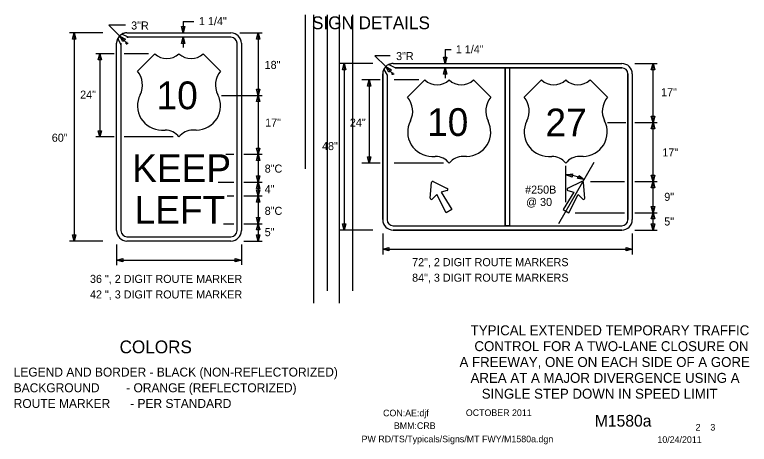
# Model space of a CAD drawing. Extents: x 16728 to 19508, y 5553 to 7079.
# Drawn here: x 17774 to 18463, y 5932 to 6334 of the extents above; entities that cross this region are included whole.
import ezdxf

# ---------------------------------------------------------------- set-up
doc = ezdxf.new("R2010")
doc.units = 0
for name, color, linetype in [('ALI_LEGAL_EX', 7, 'Continuous'), ('BORDER', 7, 'Continuous'), ('BORDER_SIGNAL_WO', 7, 'Continuous'), ('TRAFFIC_SIGNS_PR', 7, 'Continuous'), ('TYPICAL_EX', 7, 'Continuous'), ('TYPICAL_TEXT_DIMEN_PR', 7, 'Continuous')]:
    doc.layers.add(name, color=color, linetype=linetype)

msp = doc.modelspace()

# ---------------------------------------------------------------- linework, layer by layer
at = {"layer": 'ALI_LEGAL_EX'}
for p, q in [((18046.81, 6189.84), (18046.81, 6334.29)), ((18054.48, 6334.29), (18054.48, 6206.79)), ((18054.48, 6334.29), (18054.48, 6063.94)), ((18067.45, 6075.61), (18067.45, 6334.29)), ((18078.48, 6334.29), (18078.48, 6206.79)), ((18078.48, 6334.29), (18078.48, 6063.94)), ((18091.45, 6075.61), (18091.45, 6334.29))]:
    msp.add_line(p, q, dxfattribs=at)
at = {"layer": 'TRAFFIC_SIGNS_PR'}
for p, q in [((17879.58, 6317.25), (17977.08, 6317.25)), ((17872, 6313.63), (17870.99, 6312.12)), ((17871.02, 6312.05), (17873.89, 6306.01)), ((17880.78, 6313.18), (17874.69, 6315.93)), ((17977.08, 6313.18), (17879.58, 6313.18)), ((17869.83, 6132), (17869.83, 6307.5)), ((17873.89, 6307.5), (17873.89, 6132)), ((17982.77, 6132), (17982.77, 6307.5)), ((17986.83, 6307.5), (17986.83, 6132)), ((18120.27, 6282.81), (18123.41, 6277.76)), ((18131.06, 6284.5), (18124.82, 6287.51)), ((18129.1, 6288.55), (18343.6, 6288.55)), ((18129.1, 6288.55), (18343.6, 6288.55)), ((18131.04, 6284.49), (18234.32, 6284.49)), ((18343.6, 6284.49), (18131.04, 6284.49)), ((18234.32, 6284.49), (18234.32, 6136.61)), ((18238.38, 6284.49), (18238.38, 6136.61)), ((18238.38, 6284.49), (18343.6, 6284.49)), ((18119.35, 6278.8), (18119.35, 6142.3)), ((18119.35, 6142.3), (18119.35, 6278.8)), ((18123.41, 6277.75), (18123.41, 6142.3)), ((18123.41, 6277.75), (18123.41, 6142.3)), ((18349.29, 6278.8), (18349.29, 6233.05)), ((18349.29, 6142.3), (18349.29, 6278.8)), ((18353.35, 6278.8), (18353.35, 6142.3)), ((18353.35, 6278.8), (18353.35, 6142.3)), ((18349.29, 6233.05), (18349.29, 6142.3)), ((18163.95, 6162.41), (18165.1, 6177.12)), ((18166.62, 6177.99), (18179.93, 6171.63)), ((18306.08, 6177.99), (18292.77, 6171.63)), ((18308.75, 6162.41), (18307.6, 6177.12)), ((18129.1, 6136.61), (18343.6, 6136.61)), ((18129.1, 6132.55), (18343.6, 6132.55)), ((18343.6, 6132.55), (18129.1, 6132.55)), ((17879.58, 6126.31), (17977.08, 6126.31)), ((17977.08, 6122.25), (17879.58, 6122.25))]:
    msp.add_line(p, q, dxfattribs=at)
for points in [[(18131.04, 6284.49), (18131.03, 6284.49)], [(18123.41, 6277.76), (18123.41, 6277.75)], [(18179.77, 6169.66), (18174.04, 6168.09), (18184.26, 6151.92), (18178.86, 6148.8), (18169.97, 6165.74), (18165.74, 6161.57)], [(18292.93, 6169.66), (18298.66, 6168.09), (18288.44, 6151.92), (18293.84, 6148.8), (18302.73, 6165.74), (18306.96, 6161.57)]]:
    msp.add_lwpolyline(points, dxfattribs=at)
msp.add_lwpolyline([(18234.32, 6284.49), (18238.38, 6284.49), (18238.38, 6136.61), (18234.32, 6136.61)], close=True, dxfattribs=at)
for centre, radius, start, end in [((17879.58, 6307.5), 9.75, 90, 180), ((17878.99, 6309.67), 7.6, 85.58319, 124.53531), ((17977.08, 6307.5), 9.75, 0, 90), ((17876.86, 6308.09), 7.06, 145.86811, 184.82317), ((17880.18, 6317.61), 4.47, 262.2432, 277.7568), ((17977.08, 6307.5), 5.69, 0, 90), ((17868.43, 6306.75), 5.51, 352.24294, 7.75653), ((18125.48, 6279.5), 6.17, 147.60925, 186.56283), ((18129.1, 6278.8), 9.75, 90, 180), ((18129.1, 6278.8), 9.75, 90, 180), ((18128.42, 6281.98), 6.6, 84.11162, 123.06374), ((18130.04, 6291.67), 7.24, 277.81035, 278.05403), ((18343.6, 6278.8), 9.75, 0, 90), ((18343.6, 6278.8), 9.75, 0, 90), ((18343.6, 6278.8), 5.69, 0, 89.99421), ((18343.6, 6278.8), 5.69, 0, 90), ((18166.16, 6177.04), 1.06, 64.48226, 175.51774), ((18306.54, 6177.04), 1.06, 4.48226, 115.51774), ((18179.47, 6170.68), 1.06, 285.9885, 64.48226), ((18293.23, 6170.68), 1.06, 115.51774, 254.0115), ((18165.01, 6162.33), 1.06, 175.51775, 314.01151), ((18307.69, 6162.33), 1.06, 225.98849, 4.48225), ((18129.1, 6142.3), 9.75, 180, 270), ((18129.1, 6142.3), 9.75, 180, 270), ((18129.1, 6142.3), 5.69, 180, 270), ((18129.1, 6142.3), 5.69, 180, 270), ((18343.6, 6142.3), 9.75, 270, 0), ((18343.6, 6142.3), 5.69, 270, 0), ((18343.6, 6142.3), 9.75, 270, 0), ((18343.6, 6142.3), 5.69, 270, 0), ((17879.58, 6132), 9.75, 180, 270), ((17879.58, 6132), 5.69, 180, 270), ((17977.08, 6132), 5.69, 270, 0), ((17977.08, 6132), 9.75, 270, 0)]:
    msp.add_arc(centre, radius, start, end, dxfattribs=at)
at = {"layer": 'TYPICAL_EX'}
for p, q in [((17889.33, 6281.5), (17905.58, 6297.75)), ((17967.33, 6281.5), (17951.08, 6297.75)), ((18142.71, 6256.89), (18158.96, 6273.14)), ((18220.71, 6256.89), (18204.46, 6273.14)), ((18251.99, 6256.89), (18268.24, 6273.14)), ((18329.99, 6256.89), (18313.74, 6273.14)), ((17912.06, 6226.21), (17915.31, 6226.21)), ((17944.6, 6226.21), (17941.35, 6226.21)), ((18165.44, 6201.6), (18168.69, 6201.6)), ((18197.98, 6201.6), (18194.73, 6201.6)), ((18274.72, 6201.6), (18277.97, 6201.6)), ((18307.26, 6201.6), (18304.01, 6201.6))]:
    msp.add_line(p, q, dxfattribs=at)
for centre, radius, start, end in [((17916.95, 6309.58), 16.42, 226.14041, 313.85958), ((17939.7, 6309.59), 16.42, 226.14042, 313.85959), ((17873.93, 6268.49), 20.16, 333.09768, 40.19361), ((17982.73, 6268.49), 20.16, 139.80639, 206.90233), ((18170.34, 6284.97), 16.42, 226.14041, 313.85958), ((18193.09, 6284.97), 16.42, 226.14042, 313.85959), ((18279.62, 6284.97), 16.42, 226.14041, 313.85958), ((18302.36, 6284.97), 16.42, 226.14042, 313.85959), ((17912.1, 6248.93), 22.73, 152.6698, 269.90132), ((17944.56, 6248.93), 22.73, 270.09868, 27.3302), ((18127.31, 6243.88), 20.16, 333.09768, 40.19361), ((18236.11, 6243.88), 20.16, 139.80639, 206.90233), ((18236.59, 6243.88), 20.16, 333.09768, 40.19361), ((18345.39, 6243.88), 20.16, 139.80639, 206.90233), ((18165.48, 6224.32), 22.73, 152.6698, 269.90132), ((18197.94, 6224.32), 22.73, 270.09868, 27.3302), ((18274.76, 6224.32), 22.73, 152.6698, 269.90132), ((18307.22, 6224.32), 22.73, 270.09868, 27.3302), ((17915.35, 6209.93), 16.28, 37.1038, 90.13853), ((17941.31, 6209.93), 16.28, 89.86147, 142.8962), ((18168.73, 6185.32), 16.28, 37.1038, 90.13853), ((18194.69, 6185.32), 16.28, 89.86147, 142.8962), ((18278.01, 6185.32), 16.28, 37.1038, 90.13853), ((18303.97, 6185.32), 16.28, 89.86147, 142.8962)]:
    msp.add_arc(centre, radius, start, end, dxfattribs=at)
at = {"layer": 'TYPICAL_TEXT_DIMEN_PR'}
for p, q in [((17878.2, 6324.53), (17862.54, 6324.53)), ((17862.54, 6324.53), (17872.78, 6314.29)), ((17932.3, 6328.01), (17932.3, 6317.25)), ((17932.3, 6328.01), (17942.41, 6328.01)), ((17857, 6317.25), (17825.71, 6317.25)), ((17828.47, 6311.38), (17830.04, 6317.25)), ((17830.04, 6317.25), (17830.04, 6122.25)), ((17830.04, 6317.25), (17831.62, 6311.38)), ((17932.3, 6317.25), (17930.73, 6323.11)), ((17930.73, 6323.11), (17932.3, 6323.11)), ((17932.3, 6323.11), (17933.87, 6323.11)), ((17933.87, 6323.11), (17932.3, 6317.25)), ((17985.37, 6317.25), (18006.33, 6317.25)), ((18000.86, 6311.38), (18002.43, 6317.25)), ((18002.43, 6317.25), (18002.43, 6258.75)), ((18002.43, 6317.25), (18004, 6311.38)), ((17830.04, 6311.38), (17828.47, 6311.38)), ((17831.62, 6311.38), (17830.04, 6311.38)), ((17872.78, 6314.29), (17879.34, 6307.74)), ((17875.81, 6309.04), (17872.78, 6314.29)), ((17872.78, 6314.29), (17878.04, 6311.26)), ((17876.92, 6310.15), (17875.81, 6309.04)), ((17878.04, 6311.26), (17876.92, 6310.15)), ((17930.78, 6307.32), (17932.35, 6313.18)), ((17932.35, 6313.18), (17932.35, 6303.43)), ((17932.35, 6313.18), (17933.92, 6307.32)), ((18002.43, 6311.38), (18000.86, 6311.38)), ((18004, 6311.38), (18002.43, 6311.38)), ((17878.13, 6307.74), (17880.55, 6307.74)), ((17879.34, 6306.53), (17879.34, 6308.95)), ((17932.35, 6307.32), (17930.78, 6307.32)), ((17933.92, 6307.32), (17932.35, 6307.32)), ((17867.46, 6297.75), (17850.33, 6297.75)), ((17852.65, 6291.88), (17854.23, 6297.75)), ((17854.23, 6297.75), (17854.23, 6219.75)), ((17854.23, 6297.75), (17855.8, 6291.88)), ((17899.7, 6297.75), (17876.82, 6297.75)), ((18126.24, 6295.83), (18112.06, 6295.83)), ((18112.06, 6295.83), (18122.21, 6285.69)), ((18177.96, 6301.7), (18177.96, 6288.55)), ((18177.96, 6301.7), (18183.48, 6301.7)), ((17854.23, 6291.88), (17852.65, 6291.88)), ((17855.8, 6291.88), (17854.23, 6291.88)), ((18177.96, 6288.55), (18176.39, 6294.41)), ((18176.39, 6294.41), (18177.96, 6294.41)), ((18177.96, 6294.41), (18179.53, 6294.41)), ((18179.53, 6294.41), (18177.96, 6288.55)), ((18110.12, 6288.55), (18078.82, 6288.55)), ((18081.59, 6282.69), (18083.16, 6288.55)), ((18083.16, 6282.69), (18081.59, 6282.69)), ((18083.16, 6288.55), (18083.16, 6132.55)), ((18083.16, 6288.55), (18084.73, 6282.69)), ((18084.73, 6282.69), (18083.16, 6282.69)), ((18122.21, 6285.69), (18128.86, 6279.04)), ((18125.25, 6280.43), (18122.21, 6285.68)), ((18122.21, 6285.68), (18127.47, 6282.65)), ((18127.47, 6282.65), (18126.36, 6281.54)), ((18176.44, 6278.62), (18178.01, 6284.49)), ((18176.44, 6278.62), (18178.01, 6284.49)), ((18178.01, 6284.49), (18178.01, 6274.74)), ((18178.01, 6284.49), (18179.58, 6278.62)), ((18178.01, 6284.49), (18179.58, 6278.62)), ((18355.72, 6288.55), (18376.68, 6288.55)), ((18371.22, 6282.69), (18372.79, 6288.55)), ((18372.79, 6282.69), (18371.22, 6282.69)), ((18372.78, 6288.55), (18372.78, 6233.3)), ((18372.79, 6288.55), (18374.36, 6282.69)), ((18374.36, 6282.69), (18372.79, 6282.69)), ((18126.36, 6281.54), (18125.25, 6280.43)), ((18127.65, 6279.04), (18130.07, 6279.04)), ((18128.86, 6277.83), (18128.86, 6280.25)), ((18178.01, 6278.62), (18176.44, 6278.62)), ((18178.01, 6278.62), (18176.44, 6278.62)), ((18179.58, 6278.62), (18178.01, 6278.62)), ((18179.58, 6278.62), (18178.01, 6278.62)), ((18116.98, 6273.14), (18099.85, 6273.14)), ((18105.15, 6267.27), (18106.72, 6273.14)), ((18106.72, 6273.14), (18106.72, 6195.14)), ((18106.72, 6273.14), (18108.29, 6267.27)), ((18153.08, 6273.14), (18130.2, 6273.14)), ((18002.43, 6258.75), (18000.86, 6264.61)), ((18000.86, 6264.61), (18002.43, 6264.61)), ((18002.43, 6264.61), (18004, 6264.61)), ((18004, 6264.61), (18002.43, 6258.75)), ((18106.72, 6267.27), (18105.15, 6267.27)), ((18108.29, 6267.27), (18106.72, 6267.27)), ((17968.22, 6258.75), (18006.33, 6258.75)), ((18000.86, 6252.88), (18002.43, 6258.75)), ((18002.43, 6258.75), (18002.43, 6203.5)), ((18002.43, 6258.75), (18004, 6252.88)), ((18002.43, 6252.88), (18000.86, 6252.88)), ((18004, 6252.88), (18002.43, 6252.88)), ((18372.79, 6233.3), (18371.22, 6239.16)), ((18371.22, 6239.16), (18372.79, 6239.16)), ((18372.79, 6239.16), (18374.36, 6239.16)), ((18374.36, 6239.16), (18372.79, 6233.3)), ((18330.17, 6233.3), (18347.32, 6233.3)), ((18355.72, 6233.3), (18376.68, 6233.3)), ((18371.22, 6227.44), (18372.79, 6233.3)), ((18372.79, 6227.44), (18371.22, 6227.44)), ((18372.78, 6233.3), (18372.78, 6178.05)), ((18372.79, 6233.3), (18374.36, 6227.44)), ((18374.36, 6227.44), (18372.79, 6227.44)), ((17854.23, 6219.75), (17852.65, 6225.61)), ((17852.65, 6225.61), (17854.23, 6225.61)), ((17854.23, 6225.61), (17855.8, 6225.61)), ((17855.8, 6225.61), (17854.23, 6219.75)), ((17867.46, 6219.75), (17850.33, 6219.75)), ((17922.82, 6219.75), (17876.82, 6219.75)), ((18002.43, 6203.5), (18000.86, 6209.36)), ((18000.86, 6209.36), (18002.43, 6209.36)), ((18002.43, 6209.36), (18004, 6209.36)), ((18004, 6209.36), (18002.43, 6203.5)), ((17972.16, 6203.5), (17979.84, 6203.5)), ((17989.2, 6203.5), (18006.33, 6203.5)), ((18000.86, 6197.63), (18002.43, 6203.5)), ((18002.43, 6203.5), (18002.43, 6177.5)), ((18002.43, 6203.5), (18004, 6197.63)), ((18106.72, 6195.14), (18105.15, 6201)), ((18105.15, 6201), (18106.72, 6201)), ((18106.72, 6201), (18108.29, 6201)), ((18108.29, 6201), (18106.72, 6195.14)), ((18002.43, 6197.63), (18000.86, 6197.63)), ((18004, 6197.63), (18002.43, 6197.63)), ((18116.98, 6195.14), (18099.85, 6195.14)), ((18176.2, 6195.14), (18130.2, 6195.14)), ((18284.38, 6138.65), (18317.62, 6196.24)), ((18291.14, 6158.8), (18291.14, 6192.8)), ((18002.43, 6177.5), (18000.86, 6183.36)), ((18000.86, 6183.36), (18002.43, 6183.36)), ((18002.43, 6183.36), (18004, 6183.36)), ((18004, 6183.36), (18002.43, 6177.5)), ((18291.17, 6184.24), (18297.16, 6185.2)), ((18296.84, 6182.08), (18291.17, 6184.24)), ((18297, 6183.64), (18296.84, 6182.08)), ((18297.16, 6185.2), (18297, 6183.64)), ((18302.15, 6180.92), (18302.84, 6182.33)), ((18308.12, 6179.79), (18302.15, 6180.92)), ((18302.84, 6182.33), (18303.52, 6183.75)), ((18303.52, 6183.75), (18308.12, 6179.79)), ((18372.79, 6178.05), (18371.22, 6183.91)), ((18371.22, 6183.91), (18372.79, 6183.91)), ((18372.79, 6183.91), (18374.36, 6183.91)), ((18374.36, 6183.91), (18372.79, 6178.05)), ((17965.14, 6177.5), (17979.84, 6177.5)), ((17989.2, 6177.5), (18006.33, 6177.5)), ((18000.86, 6171.63), (18002.43, 6177.5)), ((18002.43, 6177.5), (18002.43, 6164.5)), ((18002.43, 6177.5), (18004, 6171.63)), ((18314.09, 6178.05), (18345.96, 6178.05)), ((18355.72, 6178.05), (18376.68, 6178.05)), ((18371.22, 6172.19), (18372.79, 6178.05)), ((18372.79, 6172.19), (18371.22, 6172.19)), ((18372.78, 6178.05), (18372.78, 6148.8)), ((18372.79, 6178.05), (18374.36, 6172.19)), ((18374.36, 6172.19), (18372.79, 6172.19)), ((18002.43, 6171.63), (18000.86, 6171.63)), ((18002.43, 6164.5), (18000.86, 6170.36)), ((18000.86, 6170.36), (18002.43, 6170.36)), ((18004, 6171.63), (18002.43, 6171.63)), ((18002.43, 6170.36), (18004, 6170.36)), ((18004, 6170.36), (18002.43, 6164.5)), ((17973.49, 6164.5), (17979.84, 6164.5)), ((17989.2, 6164.5), (18006.33, 6164.5)), ((18000.86, 6158.63), (18002.43, 6164.5)), ((18002.43, 6158.63), (18000.86, 6158.63)), ((18002.43, 6164.5), (18002.43, 6138.5)), ((18002.43, 6164.5), (18004, 6158.63)), ((18004, 6158.63), (18002.43, 6158.63)), ((18372.79, 6148.8), (18371.22, 6154.66)), ((18371.22, 6154.66), (18372.79, 6154.66)), ((18372.79, 6154.66), (18374.36, 6154.66)), ((18374.36, 6154.66), (18372.79, 6148.8)), ((18002.43, 6138.5), (18000.86, 6144.36)), ((18000.86, 6144.36), (18002.43, 6144.36)), ((18002.43, 6144.36), (18004, 6144.36)), ((18004, 6144.36), (18002.43, 6138.5)), ((18299.96, 6148.8), (18345.96, 6148.8)), ((18355.72, 6148.8), (18376.68, 6148.8)), ((18371.22, 6142.94), (18372.79, 6148.8)), ((18372.78, 6148.8), (18372.78, 6132.55)), ((18372.79, 6148.8), (18374.36, 6142.94)), ((17969.99, 6138.5), (17979.84, 6138.5)), ((17989.2, 6138.5), (18006.33, 6138.5)), ((18000.86, 6132.63), (18002.43, 6138.5)), ((18002.43, 6138.5), (18002.43, 6122.25)), ((18002.43, 6138.5), (18004, 6132.63)), ((18083.16, 6132.55), (18081.59, 6138.41)), ((18081.59, 6138.41), (18083.16, 6138.41)), ((18083.16, 6138.41), (18084.73, 6138.41)), ((18084.73, 6138.41), (18083.16, 6132.55)), ((18372.79, 6142.94), (18371.22, 6142.94)), ((18372.79, 6132.55), (18371.22, 6138.41)), ((18371.22, 6138.41), (18372.79, 6138.41)), ((18374.36, 6142.94), (18372.79, 6142.94)), ((18372.79, 6138.41), (18374.36, 6138.41)), ((18374.36, 6138.41), (18372.79, 6132.55)), ((18002.43, 6132.63), (18000.86, 6132.63)), ((18004, 6132.63), (18002.43, 6132.63)), ((18110.12, 6132.55), (18078.82, 6132.55)), ((18355.72, 6132.55), (18372.85, 6132.55)), ((18355.72, 6132.55), (18376.68, 6132.55)), ((18355.72, 6132.55), (18372.85, 6132.55)), ((17830.04, 6122.25), (17828.47, 6128.11)), ((17828.47, 6128.11), (17830.04, 6128.11)), ((17830.04, 6128.11), (17831.62, 6128.11)), ((17831.62, 6128.11), (17830.04, 6122.25)), ((18002.43, 6122.25), (18000.86, 6128.11)), ((18000.86, 6128.11), (18002.43, 6128.11)), ((18002.43, 6128.11), (18004, 6128.11)), ((18004, 6128.11), (18002.43, 6122.25)), ((18119.35, 6129.2), (18119.35, 6109.64)), ((18353.35, 6129.2), (18353.35, 6109.64)), ((17857, 6122.25), (17825.71, 6122.25)), ((17869.83, 6118.9), (17869.83, 6099.55)), ((17986.83, 6118.9), (17986.83, 6100.01)), ((17989.2, 6122.25), (18006.33, 6122.25)), ((18119.35, 6114.58), (18125.21, 6116.15)), ((18119.35, 6114.58), (18353.35, 6114.58)), ((18125.21, 6113.01), (18119.35, 6114.58)), ((18125.21, 6116.15), (18125.21, 6114.58)), ((18125.21, 6114.58), (18125.21, 6113.01)), ((18347.49, 6114.58), (18347.49, 6116.15)), ((18347.49, 6116.15), (18353.35, 6114.58)), ((18353.35, 6114.58), (18347.49, 6113.01)), ((18347.49, 6113.01), (18347.49, 6114.58)), ((17869.83, 6104.27), (17875.69, 6105.85)), ((17869.83, 6104.27), (17986.83, 6104.27)), ((17875.69, 6102.7), (17869.83, 6104.27)), ((17875.69, 6105.85), (17875.69, 6104.27)), ((17875.69, 6104.27), (17875.69, 6102.7)), ((17980.97, 6104.27), (17980.97, 6105.85)), ((17980.97, 6105.85), (17986.83, 6104.27)), ((17986.83, 6104.27), (17980.97, 6102.7)), ((17980.97, 6102.7), (17980.97, 6104.27))]:
    msp.add_line(p, q, dxfattribs=at)
msp.add_arc((18291.33, 6149.8), 34.39, 60.74521, 90.32117, dxfattribs=at)

# ---------------------------------------------------------------- texts
at = {"layer": 'BORDER'}
for s, p in [('TYPICAL EXTENDED TEMPORARY TRAFFIC', (18201.85, 6033.97)), ('CONTROL FOR A TWO-LANE CLOSURE ON', (18205.35, 6019.11)), ('A FREEWAY, ONE ON EACH SIDE OF A GORE', (18191.37, 6004.27)), ('AREA AT A MAJOR DIVERGENCE USING A', (18201.72, 5989.41)), ('SINGLE STEP DOWN IN SPEED LIMIT', (18212.22, 5974.57))]:
    msp.add_text(s, height=9.3, dxfattribs=at).set_placement(p)
at = {"layer": 'BORDER_SIGNAL_WO'}
for s, height, p in [('CON:AE:djf  ', 6.2, (18119.69, 5958.06)), ('    OCTOBER 2011    ', 6.2, (18188.08, 5958.34)), ('    M1580a   ', 11, (18301.86, 5948.38)), ('BMM:CRB   ', 6.2, (18129.81, 5946.17)), (' 2    3 ', 6.2, (18410.45, 5944.7)), ('PW RD/TS/Typicals/Signs/MT FWY/M1580a.dgn      ', 6.2, (18099.55, 5933.71)), ('10/24/2011    ', 6.2, (18376.93, 5933.13))]:
    msp.add_text(s, height=height, dxfattribs=at).set_placement(p)
at = {"layer": 'TRAFFIC_SIGNS_PR'}
for s, p in [('10', (17907.3, 6245.75)), ('10', (18160.95, 6220.68)), ('27', (18271.96, 6220.32)), ('KEEP', (17884.43, 6177.5)), ('LEFT', (17886.67, 6138.5))]:
    msp.add_text(s, height=26, dxfattribs=at).set_placement(p)
at = {"layer": 'TYPICAL_TEXT_DIMEN_PR'}
for s, height, p in [('1 1/4"', 7.55, (17947.1, 6324.5)), ('SIGN DETAILS', 12, (18053.06, 6320.72)), ('3"R', 7.55, (17883.47, 6320.41)), ('1 1/4"', 7.55, (18187.89, 6298.12)), ('3"R', 7.55, (18131.88, 6291.75)), ('18"', 7.55, (18008.67, 6283.52)), ('24"', 7.55, (17835.67, 6255.63)), ('17"', 7.55, (18380.36, 6257.91)), ('17"', 7.55, (18009.13, 6229.47)), ('24"', 7.55, (18088.58, 6229.47)), ('60"', 7.55, (17809.07, 6215.26)), ('48"', 7.55, (18062.46, 6207.45)), ('17"', 7.55, (18381.56, 6201.55)), ('8"C', 7.55, (18008.71, 6186.35)), ('4" ', 7.55, (18008.71, 6167.09)), ('#250B', 7.55, (18252.91, 6166.64)), ('9"', 7.55, (18383.34, 6159.89)), ('@ 30', 7.55, (18253.86, 6155.09)), ('8"C', 7.55, (18008.71, 6146.77)), ('5"', 7.55, (18383.34, 6136.79)), ('5" ', 7.55, (18008.71, 6126.79)), ('72", 2 DIGIT ROUTE MARKERS', 7.55, (18146.93, 6098.71)), ('36 ", 2 DIGIT ROUTE MARKER', 7.55, (17844.88, 6083.01)), ('84", 3 DIGIT ROUTE MARKERS', 7.55, (18146.93, 6084.16)), ('42 ", 3 DIGIT ROUTE MARKER', 7.55, (17844.88, 6068.47)), ('COLORS', 12, (17872.65, 6017.08)), ('LEGEND AND BORDER - BLACK (NON-REFLECTORIZED)', 8.4, (17773.37, 5995.3)), ('BACKGROUND        - ORANGE (REFLECTORIZED)', 8.4, (17773.37, 5980.6)), ('ROUTE MARKER      - PER STANDARD', 8.4, (17773.37, 5965.9))]:
    msp.add_text(s, height=height, dxfattribs=at).set_placement(p)

doc.saveas('drawing.dxf')
